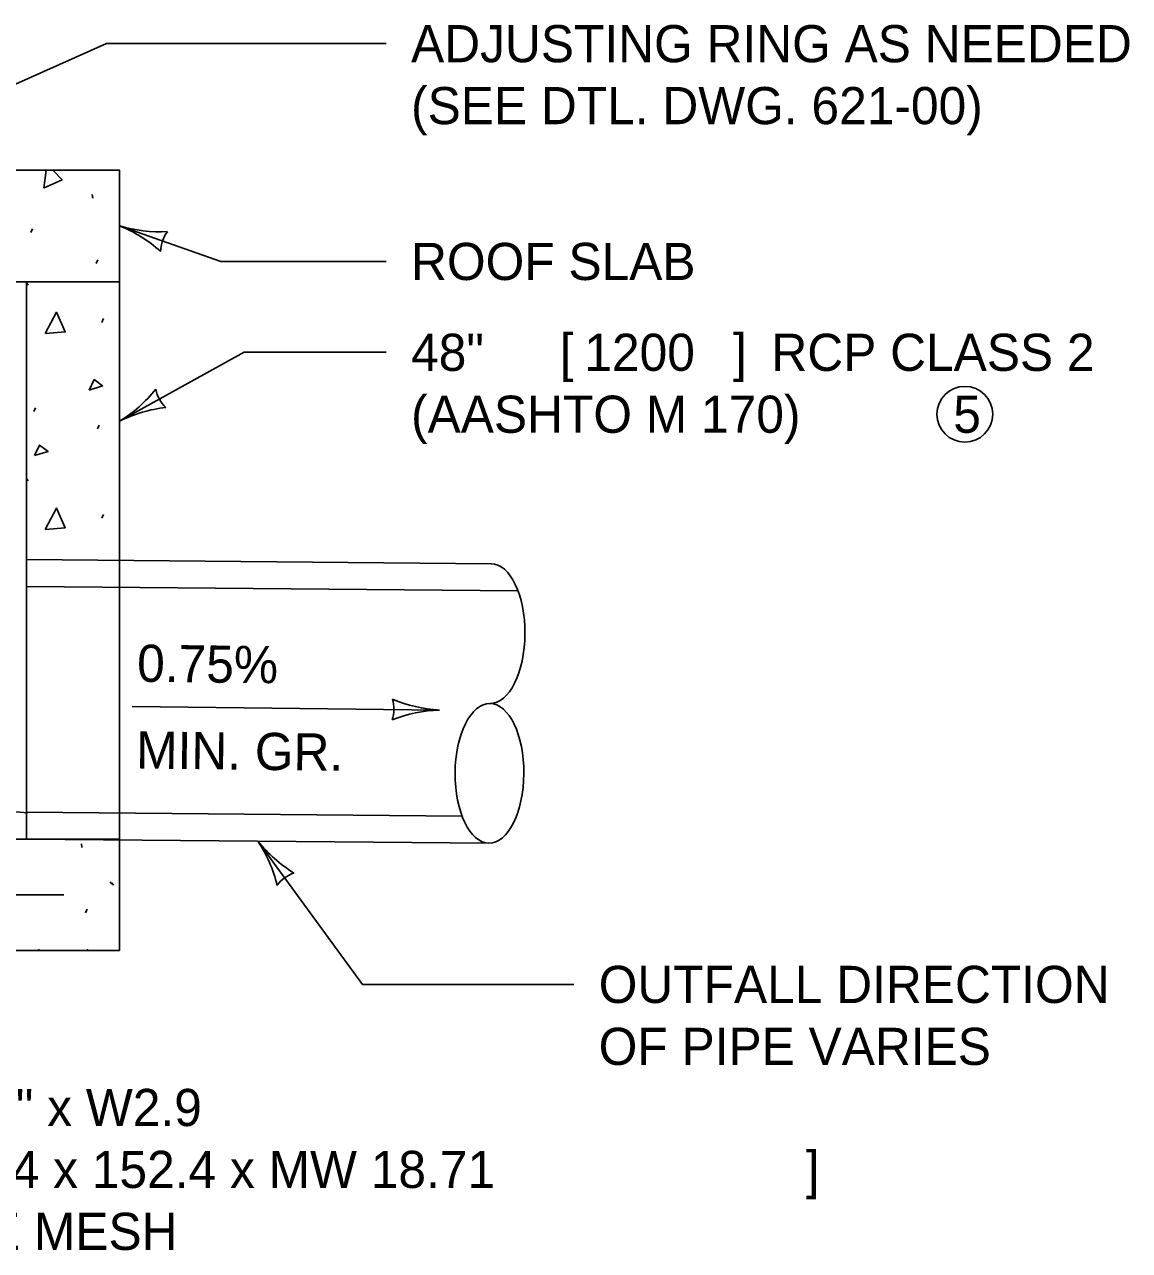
# Model space of a CAD drawing. Extents: x 49991.4 to 50041.6, y 49987.6 to 50011.4.
# Drawn here: x 50027.575 to 50029.359, y 49990.663 to 49992.642 of the extents above; entities that cross this region are included whole.
import ezdxf

# ---------------------------------------------------------------- set-up
doc = ezdxf.new("R2010")
doc.units = 0
for name, color, linetype in [('Level 1', 7, 'Continuous'), ('Level 2', 7, 'Continuous'), ('Level 3', 7, 'Continuous'), ('Level 4', 7, 'Continuous')]:
    doc.layers.add(name, color=color, linetype=linetype)

msp = doc.modelspace()

# ---------------------------------------------------------------- linework, layer by layer
at = {"layer": 'Level 1'}
for p, q in [((50027.6847, 49992.3679), (50027.6854, 49992.3619)), ((50027.5854, 49992.3064), (50027.5881, 49992.3125)), ((50027.691, 49992.2563), (50027.6937, 49992.2624)), ((50027.7287, 49992.2269), (50027.7287, 49991.7764)), ((50027.5787, 49991.7781), (50028.3284, 49991.7714)), ((50027.5787, 49991.7349), (50028.3718, 49991.7279)), ((50026.1432, 49991.4897), (50027.5803, 49991.3695)), ((50027.5787, 49991.3702), (50028.2816, 49991.3639)), ((50027.5787, 49991.3269), (50028.325, 49991.3203)), ((50027.6673, 49991.3195), (50027.6679, 49991.3134)), ((50027.7135, 49991.258), (50027.7162, 49991.2539)), ((50027.7162, 49991.2564), (50027.7189, 49991.2524)), ((50027.6387, 49991.2369), (50026.0832, 49991.2369)), ((50027.6735, 49991.2078), (50027.6762, 49991.2139)), ((50025.9932, 49991.1469), (50027.7287, 49991.1469)), ((50027.5977, 49991.149), (50027.5991, 49991.1469))]:
    msp.add_line(p, q, dxfattribs=at)
msp.add_lwpolyline([(50025.9932, 49992.2269), (50025.9932, 49992.4069), (50027.7287, 49992.4069), (50027.7287, 49992.2269)], close=True, dxfattribs=at)
for points in [[(50027.6062, 49992.3779), (50027.6102, 49992.4069)], [(50027.6209, 49992.4069), (50027.6358, 49992.3916), (50027.6068, 49992.3782)], [(50027.7287, 49992.2269), (50027.5787, 49992.2269), (50027.5787, 49991.3269)], [(50025.9932, 49991.1469), (50025.9932, 49991.3269), (50027.7287, 49991.3269), (50027.7287, 49991.1469)], [(50027.6763, 49991.1469), (50027.6769, 49991.1483), (50027.6787, 49991.1469)]]:
    msp.add_lwpolyline(points, dxfattribs=at)
msp.add_ellipse((50028.3276, 49991.6587), major_axis=(0.0008, 0.1128), ratio=0.492218, start_param=3.141593, end_param=6.283185, dxfattribs=at)
msp.add_ellipse((50028.3259, 49991.4331), major_axis=(0.0008, 0.1128), ratio=0.492224, dxfattribs=at)
at = {"layer": 'Level 2'}
msp.add_circle((50029.0933, 49992.0129), 0.045, dxfattribs=at)
at = {"layer": 'Level 3'}
for p, q in [((50027.4497, 49992.4969), (50027.7078, 49992.6112)), ((50027.7078, 49992.6112), (50028.1593, 49992.6112)), ((50027.7287, 49992.3169), (50027.8921, 49992.2596)), ((50027.8921, 49992.2596), (50028.1593, 49992.2596)), ((50027.7287, 49992.0017), (50027.9297, 49992.1129)), ((50027.9297, 49992.1129), (50028.1593, 49992.1129)), ((50027.7492, 49991.5411), (50028.2451, 49991.5353)), ((50027.9519, 49991.3236), (50028.1208, 49991.0923)), ((50028.1208, 49991.0923), (50028.4622, 49991.0923))]:
    msp.add_line(p, q, dxfattribs=at)
for centre, radius, start, end in [((50027.6466, 49992.1104), 0.2223, 48.1316, 68.3151), ((50027.7949, 49992.5404), 0.233, 253.5029, 272.7528), ((50027.6466, 49992.1104), 0.2223, 48.1316, 68.3151), ((50027.7949, 49992.5404), 0.233, 253.5029, 272.7528), ((50027.8497, 49992.2745), 0.0548, 142.8144, 178.5368), ((50027.8497, 49992.2745), 0.0548, 142.8144, 178.5368), ((50027.606, 49992.1997), 0.233, 301.7889, 321.0388), ((50027.606, 49992.1997), 0.233, 301.7889, 321.0388), ((50027.8409, 49992.0637), 0.0548, 191.1005, 226.8228), ((50027.8409, 49992.0637), 0.0548, 191.1005, 226.8228), ((50027.8283, 49991.8029), 0.2223, 96.4176, 116.6012), ((50027.8283, 49991.8029), 0.2223, 96.4176, 116.6012), ((50028.1169, 49991.5368), 0.0548, 341.4691, 17.1914), ((50028.2568, 49991.7573), 0.2223, 246.7863, 266.9698), ((50028.2539, 49991.3025), 0.233, 92.1576, 111.4074), ((50027.7671, 49991.2), 0.2223, 13.5954, 33.7789), ((50028.133, 49991.4702), 0.233, 218.9667, 238.2165), ((50027.7671, 49991.2), 0.2223, 13.5954, 33.7789), ((50028.133, 49991.4702), 0.233, 218.9667, 238.2165), ((50028.0275, 49991.2201), 0.0548, 108.2782, 144.0005), ((50028.0275, 49991.2201), 0.0548, 108.2782, 144.0005)]:
    msp.add_arc(centre, radius, start, end, dxfattribs=at)
at = {"layer": 'Level 4'}
for p, q in [((50027.5787, 49992.2254), (50027.5814, 49992.2213)), ((50027.6999, 49992.1612), (50027.7026, 49992.1673)), ((50027.5902, 49992.0171), (50027.5929, 49992.0232)), ((50027.6931, 49991.9893), (50027.6958, 49991.9954)), ((50027.5787, 49991.9093), (50027.5814, 49991.9053)), ((50027.6999, 49991.8451), (50027.7026, 49991.8512)), ((50027.7287, 49991.7764), (50027.7287, 49991.3258))]:
    msp.add_line(p, q, dxfattribs=at)
for points in [[(50027.6085, 49992.143), (50027.6268, 49992.1775), (50027.641, 49992.1457), (50027.6092, 49992.143)], [(50027.6797, 49992.052), (50027.6878, 49992.0689), (50027.7013, 49992.0587), (50027.6797, 49992.052)], [(50027.5916, 49991.946), (50027.5997, 49991.963), (50027.6132, 49991.9528), (50027.5916, 49991.946)], [(50027.6085, 49991.8269), (50027.6268, 49991.8614), (50027.641, 49991.8296), (50027.6092, 49991.8269)]]:
    msp.add_lwpolyline(points, dxfattribs=at)

# ---------------------------------------------------------------- texts
at = {"layer": 'Level 2'}
for s, rotation, p in [('ADJUSTING RING AS NEEDED', 360, (50028.1993, 49992.5812)), ('(SEE DTL. DWG. 621-00)', 360, (50028.1993, 49992.4812)), ('ROOF SLAB', 360, (50028.1993, 49992.2296)), ('48" ', 360, (50028.1993, 49992.0829)), ('[', 360, (50028.4393, 49992.0829)), ('1200', 360, (50028.479, 49992.0829)), (']', 360, (50028.719, 49992.0829)), (' RCP CLASS 2', 360, (50028.7587, 49992.0829)), ('(AASHTO M 170)', 360, (50028.1993, 49991.9829)), ('0.75%', 359.3303, (50027.7568, 49991.581)), ('MIN. GR.', 359.3303, (50027.7552, 49991.441)), ('OUTFALL DIRECTION', 360, (50028.5022, 49991.0623)), ('OF PIPE VARIES', 360, (50028.5022, 49990.9623)), ('6" x 6" x W2.9', 360, (50027.3587, 49990.8636)), ('152.4 x 152.4 x MW 18.71', 360, (50027.3984, 49990.7636)), (']', 360, (50028.8365, 49990.7636)), ('WIRE MESH', 360, (50027.3587, 49990.6636))]:
    msp.add_text(s, height=0.06, rotation=rotation, dxfattribs=at).set_placement(p)
msp.add_text('5', height=0.06, dxfattribs=at).set_placement((50029.0746, 49991.9829))

doc.saveas('drawing.dxf')
